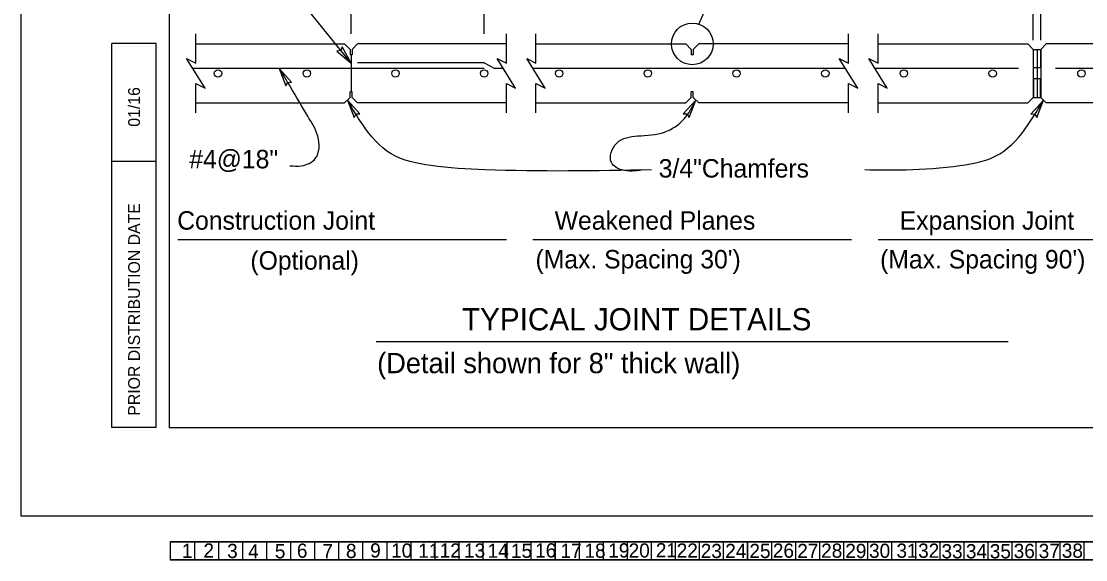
# Model space of a CAD drawing. Extents: x 0 to 2.83, y -0.03 to 1.83.
# Drawn here: x 0 to 0.75, y -0.031 to 0.349 of the extents above; entities that cross this region are included whole.
import ezdxf

# ---------------------------------------------------------------- set-up
doc = ezdxf.new("R2010")
doc.units = 0
for name, color, linetype in [('1', 7, 'Continuous'), ('10', 7, 'Continuous'), ('11', 7, 'Continuous'), ('12', 7, 'Continuous'), ('13', 7, 'Continuous'), ('14', 7, 'Continuous'), ('15', 7, 'Continuous'), ('16', 7, 'Continuous'), ('17', 7, 'Continuous'), ('18', 7, 'Continuous'), ('19', 7, 'Continuous'), ('2', 7, 'Continuous'), ('20', 7, 'Continuous'), ('21', 7, 'Continuous'), ('22', 7, 'Continuous'), ('23', 7, 'Continuous'), ('24', 7, 'Continuous'), ('25', 7, 'Continuous'), ('26', 7, 'Continuous'), ('27', 7, 'Continuous'), ('28', 7, 'Continuous'), ('29', 7, 'Continuous'), ('3', 7, 'Continuous'), ('30', 7, 'Continuous'), ('31', 7, 'Continuous'), ('32', 7, 'Continuous'), ('33', 7, 'Continuous'), ('34', 7, 'Continuous'), ('35', 7, 'Continuous'), ('36', 7, 'Continuous'), ('37', 7, 'Continuous'), ('38', 7, 'Continuous'), ('4', 7, 'Continuous'), ('5', 7, 'Continuous'), ('50', 7, 'Continuous'), ('51', 7, 'Continuous'), ('54', 7, 'Continuous'), ('55', 7, 'Continuous'), ('57', 7, 'Continuous'), ('6', 7, 'Continuous'), ('62', 7, 'Continuous'), ('63', 7, 'Continuous'), ('7', 7, 'Continuous'), ('8', 7, 'Continuous'), ('9', 7, 'Continuous')]:
    doc.layers.add(name, color=color, linetype=linetype)

msp = doc.modelspace()

# ---------------------------------------------------------------- linework, layer by layer
at = {"layer": '50'}
for p, q in [((0.47716, 0.34686), (0.50685, 0.41239)), ((0.12292, 0.33297), (0.22773, 0.33297)), ((0.22773, 0.33297), (0.23164, 0.32906)), ((0.23686, 0.33297), (0.23294, 0.32906)), ((0.34167, 0.33297), (0.23686, 0.33297)), ((0.3625, 0.33297), (0.46796, 0.33297)), ((0.46796, 0.33297), (0.47187, 0.32906)), ((0.46796, 0.33297), (0.47187, 0.32906)), ((0.4771, 0.33297), (0.47318, 0.32906)), ((0.4771, 0.33297), (0.47318, 0.32906)), ((0.58255, 0.33297), (0.4771, 0.33297)), ((0.60339, 0.33297), (0.70886, 0.33297)), ((0.70886, 0.33297), (0.71276, 0.32906)), ((0.72188, 0.33297), (0.71797, 0.32906)), ((0.82735, 0.33297), (0.72188, 0.33297)), ((0.23164, 0.32906), (0.23164, 0.32514)), ((0.23294, 0.32514), (0.23164, 0.32514)), ((0.23229, 0.32514), (0.23229, 0.29913)), ((0.23294, 0.32906), (0.23294, 0.32514)), ((0.47187, 0.32906), (0.47187, 0.32514)), ((0.47187, 0.32906), (0.47187, 0.32514)), ((0.47318, 0.32514), (0.47187, 0.32514)), ((0.47318, 0.32514), (0.47187, 0.32514)), ((0.47318, 0.32906), (0.47318, 0.32514)), ((0.47318, 0.32906), (0.47318, 0.32514)), ((0.71276, 0.32906), (0.71276, 0.29521)), ((0.71537, 0.32906), (0.71537, 0.29521)), ((0.71797, 0.32906), (0.71797, 0.29521)), ((0.22773, 0.2913), (0.23164, 0.29521)), ((0.23164, 0.29521), (0.23164, 0.29913)), ((0.23294, 0.29913), (0.23164, 0.29913)), ((0.23294, 0.29521), (0.23294, 0.29913)), ((0.23686, 0.2913), (0.23294, 0.29521)), ((0.46796, 0.2913), (0.47187, 0.29521)), ((0.46796, 0.2913), (0.47187, 0.29521)), ((0.47187, 0.29521), (0.47187, 0.29913)), ((0.47318, 0.29913), (0.47187, 0.29913)), ((0.47187, 0.29521), (0.47187, 0.29913)), ((0.47318, 0.29913), (0.47187, 0.29913)), ((0.47318, 0.29521), (0.47318, 0.29913)), ((0.47318, 0.29521), (0.47318, 0.29913)), ((0.4771, 0.2913), (0.47318, 0.29521)), ((0.4771, 0.2913), (0.47318, 0.29521)), ((0.70886, 0.2913), (0.71276, 0.29521)), ((0.72188, 0.2913), (0.71797, 0.29521)), ((0.12292, 0.2913), (0.22773, 0.2913)), ((0.34167, 0.2913), (0.23686, 0.2913)), ((0.3625, 0.2913), (0.46796, 0.2913)), ((0.58255, 0.2913), (0.4771, 0.2913)), ((0.60339, 0.2913), (0.70886, 0.2913)), ((0.82735, 0.2913), (0.72188, 0.2913))]:
    msp.add_line(p, q, dxfattribs=at)
for points in [[(0.71791, 0.32906), (0.71791, 0.31604), (0.71282, 0.31604), (0.71282, 0.32906)], [(0.71791, 0.29521), (0.71791, 0.30823), (0.71282, 0.30823), (0.71282, 0.29521)]]:
    msp.add_lwpolyline(points, close=True, dxfattribs=at)
msp.add_circle((0.47257, 0.33293), 0.01467, dxfattribs=at)
at = {"layer": '51'}
for p, q in [((0.32604, 0.31561), (0.12077, 0.31561)), ((0.32604, 0.31951), (0.23686, 0.31951)), ((0.32604, 0.31951), (0.33341, 0.31561)), ((0.33952, 0.31561), (0.33341, 0.31561)), ((0.5804, 0.31561), (0.36035, 0.31561)), ((0.70235, 0.31561), (0.60123, 0.31561)), ((0.82519, 0.31561), (0.72839, 0.31561))]:
    msp.add_line(p, q, dxfattribs=at)
for centre in [(0.13854, 0.31213), (0.20104, 0.31213), (0.26354, 0.31213), (0.32604, 0.31213), (0.37878, 0.31213), (0.44128, 0.31213), (0.50378, 0.31213), (0.56628, 0.31213), (0.62162, 0.31213), (0.68412, 0.31213), (0.74662, 0.31213)]:
    msp.add_circle(centre, 0.0026, dxfattribs=at)
at = {"layer": '54'}
for points in [[(0.23229, 0.31939), (0.22594, 0.33097), (0.22505, 0.3283), (0.22233, 0.32784)], [(0.18161, 0.31561), (0.1864, 0.3033), (0.18763, 0.30583), (0.19039, 0.30593)], [(0.22968, 0.29326), (0.23454, 0.28097), (0.23575, 0.28351), (0.23851, 0.28363)], [(0.47514, 0.29326), (0.46617, 0.28356), (0.46899, 0.28356), (0.47029, 0.28113)], [(0.71992, 0.29325), (0.71104, 0.28348), (0.71385, 0.28351), (0.71517, 0.28109)]]:
    msp.add_lwpolyline(points, close=True, dxfattribs=at)
at = {"layer": '55'}
for p, q in [((0.23229, 0.3401), (0.23229, 0.37681)), ((0.32604, 0.3401), (0.32604, 0.37681)), ((0.71276, 0.33555), (0.71276, 0.37681)), ((0.71797, 0.33555), (0.71797, 0.37681)), ((0.23229, 0.31939), (0.19647, 0.36376)), ((0.12292, 0.31937), (0.12292, 0.3401)), ((0.34167, 0.31937), (0.34167, 0.3401)), ((0.3625, 0.31937), (0.3625, 0.3401)), ((0.58255, 0.31937), (0.58255, 0.3401)), ((0.60339, 0.31937), (0.60339, 0.3401)), ((0.12943, 0.30164), (0.11641, 0.32263)), ((0.11641, 0.32263), (0.12292, 0.31937)), ((0.34818, 0.30164), (0.33516, 0.32263)), ((0.33516, 0.32263), (0.34167, 0.31937)), ((0.36901, 0.30164), (0.35599, 0.32263)), ((0.35599, 0.32263), (0.3625, 0.31937)), ((0.58906, 0.30164), (0.57604, 0.32263)), ((0.57604, 0.32263), (0.58255, 0.31937)), ((0.6099, 0.30164), (0.59688, 0.32263)), ((0.59688, 0.32263), (0.60339, 0.31937)), ((0.12292, 0.28426), (0.12292, 0.3049)), ((0.12292, 0.3049), (0.12943, 0.30164)), ((0.34167, 0.28426), (0.34167, 0.3049)), ((0.34167, 0.3049), (0.34818, 0.30164)), ((0.3625, 0.28426), (0.3625, 0.3049)), ((0.3625, 0.3049), (0.36901, 0.30164)), ((0.58255, 0.28426), (0.58255, 0.3049)), ((0.58255, 0.3049), (0.58906, 0.30164)), ((0.60339, 0.28426), (0.60339, 0.3049)), ((0.60339, 0.3049), (0.6099, 0.30164))]:
    msp.add_line(p, q, dxfattribs=at)
for points in [[(0.18912, 0.24701), (0.19726, 0.24701), (0.20707, 0.25202), (0.20874, 0.26788), (0.20185, 0.28186), (0.18954, 0.30272), (0.18161, 0.31561)], [(0.44389, 0.24405), (0.32652, 0.24419), (0.28855, 0.24713), (0.26048, 0.25542), (0.24043, 0.27601), (0.22968, 0.29326)], [(0.43739, 0.24404), (0.42298, 0.24403), (0.41561, 0.24934), (0.41937, 0.26293), (0.43411, 0.26801), (0.45311, 0.2708), (0.46671, 0.27997), (0.47514, 0.29326)], [(0.59404, 0.24426), (0.62309, 0.24419), (0.66105, 0.24713), (0.68912, 0.25542), (0.70918, 0.27601), (0.71992, 0.29325)]]:
    msp.add_spline(points, degree=3, dxfattribs=at)
at = {"layer": '57'}
for p, q in [((0.1102, 0.19492), (0.34167, 0.19492)), ((0.36023, 0.19492), (0.58482, 0.19492)), ((0.60339, 0.19492), (0.82746, 0.19492)), ((0.24991, 0.12316), (0.69514, 0.12316))]:
    msp.add_line(p, q, dxfattribs=at)
at = {"layer": '62'}
for p, q in [((0.10494, -0.01804), (1.17174, -0.01804)), ((0.10494, -0.01804), (0.10494, -0.03074)), ((0.10496, -0.0181), (1.17175, -0.0181)), ((0.10496, -0.0181), (0.10496, -0.0308)), ((0.12188, -0.01804), (0.12188, -0.03074)), ((0.12189, -0.0181), (0.12189, -0.0308)), ((0.13881, -0.01804), (0.13881, -0.03074)), ((0.13882, -0.0181), (0.13882, -0.0308)), ((0.15574, -0.01804), (0.15574, -0.03074)), ((0.15576, -0.0181), (0.15576, -0.0308)), ((0.17267, -0.01804), (0.17267, -0.03074)), ((0.17269, -0.0181), (0.17269, -0.0308)), ((0.18961, -0.01804), (0.18961, -0.03074)), ((0.18962, -0.0181), (0.18962, -0.0308)), ((0.20654, -0.01804), (0.20654, -0.03074)), ((0.20656, -0.0181), (0.20656, -0.0308)), ((0.22348, -0.01804), (0.22348, -0.03074)), ((0.22349, -0.0181), (0.22349, -0.0308)), ((0.24041, -0.01804), (0.24041, -0.03074)), ((0.24042, -0.0181), (0.24042, -0.0308)), ((0.25734, -0.01804), (0.25734, -0.03074)), ((0.25736, -0.0181), (0.25736, -0.0308)), ((0.27427, -0.01804), (0.27427, -0.03074)), ((0.27429, -0.0181), (0.27429, -0.0308)), ((0.29121, -0.01804), (0.29121, -0.03074)), ((0.29122, -0.0181), (0.29122, -0.0308)), ((0.30814, -0.01804), (0.30814, -0.03074)), ((0.30816, -0.0181), (0.30816, -0.0308)), ((0.32508, -0.01804), (0.32508, -0.03074)), ((0.32509, -0.0181), (0.32509, -0.0308)), ((0.34201, -0.01804), (0.34201, -0.03074)), ((0.34202, -0.0181), (0.34202, -0.0308)), ((0.35894, -0.01804), (0.35894, -0.03074)), ((0.35896, -0.0181), (0.35896, -0.0308)), ((0.37588, -0.01804), (0.37588, -0.03074)), ((0.37589, -0.0181), (0.37589, -0.0308)), ((0.39281, -0.01804), (0.39281, -0.03074)), ((0.39282, -0.0181), (0.39282, -0.0308)), ((0.40974, -0.01804), (0.40974, -0.03074)), ((0.40976, -0.0181), (0.40976, -0.0308)), ((0.42668, -0.01804), (0.42668, -0.03074)), ((0.42669, -0.0181), (0.42669, -0.0308)), ((0.44361, -0.01804), (0.44361, -0.03074)), ((0.44362, -0.0181), (0.44362, -0.0308)), ((0.46054, -0.01804), (0.46054, -0.03074)), ((0.46056, -0.0181), (0.46056, -0.0308)), ((0.47748, -0.01804), (0.47748, -0.03074)), ((0.47749, -0.0181), (0.47749, -0.0308)), ((0.49441, -0.01804), (0.49441, -0.03074)), ((0.49442, -0.0181), (0.49442, -0.0308)), ((0.51134, -0.01804), (0.51134, -0.03074)), ((0.51136, -0.0181), (0.51136, -0.0308)), ((0.52828, -0.01804), (0.52828, -0.03074)), ((0.52829, -0.0181), (0.52829, -0.0308)), ((0.54521, -0.01804), (0.54521, -0.03074)), ((0.54522, -0.0181), (0.54522, -0.0308)), ((0.56214, -0.01804), (0.56214, -0.03074)), ((0.56216, -0.0181), (0.56216, -0.0308)), ((0.57908, -0.01804), (0.57908, -0.03074)), ((0.57909, -0.0181), (0.57909, -0.0308)), ((0.59601, -0.01804), (0.59601, -0.03074)), ((0.59602, -0.0181), (0.59602, -0.0308)), ((0.61294, -0.01804), (0.61294, -0.03074)), ((0.61296, -0.0181), (0.61296, -0.0308)), ((0.62988, -0.01804), (0.62988, -0.03074)), ((0.62989, -0.0181), (0.62989, -0.0308)), ((0.64681, -0.01804), (0.64681, -0.03074)), ((0.64682, -0.0181), (0.64682, -0.0308)), ((0.66374, -0.01804), (0.66374, -0.03074)), ((0.66376, -0.0181), (0.66376, -0.0308)), ((0.68068, -0.01804), (0.68068, -0.03074)), ((0.68069, -0.0181), (0.68069, -0.0308)), ((0.69761, -0.01804), (0.69761, -0.03074)), ((0.69762, -0.0181), (0.69762, -0.0308)), ((0.71454, -0.01804), (0.71454, -0.03074)), ((0.71456, -0.0181), (0.71456, -0.0308)), ((0.73147, -0.01804), (0.73147, -0.03074)), ((0.73149, -0.0181), (0.73149, -0.0308)), ((0.74841, -0.01804), (0.74841, -0.03074)), ((0.74842, -0.0181), (0.74842, -0.0308)), ((0.10494, -0.03074), (1.17174, -0.03074)), ((0.10496, -0.0308), (1.17175, -0.0308))]:
    msp.add_line(p, q, dxfattribs=at)
at = {"layer": '63'}
for p, q in [((0, 0), (0, 1.83333)), ((0.06381, 0.06244), (0.06381, 0.33328)), ((0.09506, 0.33328), (0.06381, 0.33328)), ((0.09506, 0.06244), (0.09506, 0.33328)), ((0.09506, 0.24994), (0.06381, 0.24994)), ((0.09506, 0.06244), (0.06381, 0.06244)), ((2.83333, 0), (0, 0))]:
    msp.add_line(p, q, dxfattribs=at)
msp.add_lwpolyline([(2.72918, 1.77077), (0.10418, 1.77077), (0.10418, 0.06244), (2.72918, 0.06244)], close=True, dxfattribs=at)

# ---------------------------------------------------------------- texts
at = {"layer": '1'}
for p in [(0.11316, -0.02944), (0.11317, -0.02949)]:
    msp.add_text('1', height=0.01, dxfattribs=at).set_placement(p)
at = {"layer": '10'}
for p in [(0.26046, -0.02928), (0.26047, -0.02934)]:
    msp.add_text('10', height=0.01, dxfattribs=at).set_placement(p)
at = {"layer": '11'}
for p in [(0.2796, -0.02937), (0.27961, -0.02942)]:
    msp.add_text('11', height=0.01, dxfattribs=at).set_placement(p)
at = {"layer": '12'}
for p in [(0.29469, -0.02925), (0.29471, -0.0293)]:
    msp.add_text('12', height=0.01, dxfattribs=at).set_placement(p)
at = {"layer": '13'}
for p in [(0.31181, -0.02928), (0.31182, -0.02933)]:
    msp.add_text('13', height=0.01, dxfattribs=at).set_placement(p)
at = {"layer": '14'}
for p in [(0.32844, -0.02939), (0.32846, -0.02944)]:
    msp.add_text('14', height=0.01, dxfattribs=at).set_placement(p)
at = {"layer": '15'}
for p in [(0.34488, -0.02946), (0.34489, -0.02951)]:
    msp.add_text('15', height=0.01, dxfattribs=at).set_placement(p)
at = {"layer": '16'}
for p in [(0.3619, -0.02918), (0.36191, -0.02923)]:
    msp.add_text('16', height=0.01, dxfattribs=at).set_placement(p)
at = {"layer": '17'}
for p in [(0.3797, -0.02946), (0.37971, -0.02951)]:
    msp.add_text('17', height=0.01, dxfattribs=at).set_placement(p)
at = {"layer": '18'}
for p in [(0.39663, -0.02938), (0.39664, -0.02943)]:
    msp.add_text('18', height=0.01, dxfattribs=at).set_placement(p)
at = {"layer": '19'}
for p in [(0.4134, -0.02918), (0.41342, -0.02923)]:
    msp.add_text('19', height=0.01, dxfattribs=at).set_placement(p)
at = {"layer": '2'}
for p in [(0.12828, -0.02928), (0.12829, -0.02934)]:
    msp.add_text('2', height=0.01, dxfattribs=at).set_placement(p)
at = {"layer": '20'}
for p in [(0.42774, -0.02926), (0.42776, -0.02931)]:
    msp.add_text('20', height=0.01, dxfattribs=at).set_placement(p)
at = {"layer": '21'}
for p in [(0.44688, -0.02909), (0.44689, -0.02914)]:
    msp.add_text('21', height=0.01, dxfattribs=at).set_placement(p)
at = {"layer": '22'}
for p in [(0.46158, -0.02929), (0.46159, -0.02934)]:
    msp.add_text('22', height=0.01, dxfattribs=at).set_placement(p)
at = {"layer": '23'}
for p in [(0.47852, -0.02958), (0.47853, -0.02963)]:
    msp.add_text('23', height=0.01, dxfattribs=at).set_placement(p)
at = {"layer": '24'}
for p in [(0.49576, -0.02958), (0.49577, -0.02963)]:
    msp.add_text('24', height=0.01, dxfattribs=at).set_placement(p)
at = {"layer": '25'}
for p in [(0.51281, -0.02958), (0.51282, -0.02963)]:
    msp.add_text('25', height=0.01, dxfattribs=at).set_placement(p)
at = {"layer": '26'}
for p in [(0.52931, -0.02936), (0.52932, -0.02941)]:
    msp.add_text('26', height=0.01, dxfattribs=at).set_placement(p)
at = {"layer": '27'}
for p in [(0.54648, -0.02958), (0.54649, -0.02963)]:
    msp.add_text('27', height=0.01, dxfattribs=at).set_placement(p)
at = {"layer": '28'}
for p in [(0.56333, -0.02938), (0.56334, -0.02943)]:
    msp.add_text('28', height=0.01, dxfattribs=at).set_placement(p)
at = {"layer": '29'}
for p in [(0.58032, -0.02956), (0.58034, -0.02961)]:
    msp.add_text('29', height=0.01, dxfattribs=at).set_placement(p)
at = {"layer": '3'}
for p in [(0.145, -0.02955), (0.14501, -0.02961)]:
    msp.add_text('3', height=0.01, dxfattribs=at).set_placement(p)
at = {"layer": '30'}
for p in [(0.59706, -0.02946), (0.59707, -0.02951)]:
    msp.add_text('30', height=0.01, dxfattribs=at).set_placement(p)
at = {"layer": '31'}
for p in [(0.61636, -0.02938), (0.61637, -0.02943)]:
    msp.add_text('31', height=0.01, dxfattribs=at).set_placement(p)
at = {"layer": '32'}
for p in [(0.63163, -0.02938), (0.63165, -0.02943)]:
    msp.add_text('32', height=0.01, dxfattribs=at).set_placement(p)
at = {"layer": '33'}
for p in [(0.64808, -0.02978), (0.64809, -0.02983)]:
    msp.add_text('33', height=0.01, dxfattribs=at).set_placement(p)
at = {"layer": '34'}
for p in [(0.66527, -0.02978), (0.66528, -0.02984)]:
    msp.add_text('34', height=0.01, dxfattribs=at).set_placement(p)
at = {"layer": '35'}
for p in [(0.68209, -0.02978), (0.68211, -0.02984)]:
    msp.add_text('35', height=0.01, dxfattribs=at).set_placement(p)
at = {"layer": '36'}
for p in [(0.69895, -0.02958), (0.69896, -0.02964)]:
    msp.add_text('36', height=0.01, dxfattribs=at).set_placement(p)
at = {"layer": '37'}
for p in [(0.71654, -0.02958), (0.71655, -0.02964)]:
    msp.add_text('37', height=0.01, dxfattribs=at).set_placement(p)
at = {"layer": '38'}
for p in [(0.73281, -0.02938), (0.73282, -0.02943)]:
    msp.add_text('38', height=0.01, dxfattribs=at).set_placement(p)
at = {"layer": '4'}
for p in [(0.15973, -0.02984), (0.15975, -0.0299)]:
    msp.add_text('4', height=0.01, dxfattribs=at).set_placement(p)
at = {"layer": '5'}
for p in [(0.17858, -0.02977), (0.17859, -0.02982)]:
    msp.add_text('5', height=0.01, dxfattribs=at).set_placement(p)
at = {"layer": '57'}
for s, height, p in [('#4@18"', 0.013017, (0.11833, 0.24518)), ('3/4"Chamfers', 0.0130167, (0.44894, 0.23867)), ('Construction Joint', 0.0130167, (0.10981, 0.20194)), ('Weakened Planes', 0.0130167, (0.37567, 0.20194)), ('Expansion Joint', 0.0130167, (0.61867, 0.20194)), ('(Optional)', 0.013017, (0.16136, 0.17376)), ("(Max. Spacing 30')", 0.0130167, (0.36214, 0.1746)), ("(Max. Spacing 90')", 0.0130167, (0.60486, 0.1746)), ('TYPICAL JOINT DETAILS', 0.015625, (0.31037, 0.13098)), ('(Detail shown for 8" thick wall)', 0.0143167, (0.25065, 0.10073))]:
    msp.add_text(s, height=height, dxfattribs=at).set_placement(p)
at = {"layer": '6'}
for p in [(0.19409, -0.02938), (0.19411, -0.02943)]:
    msp.add_text('6', height=0.01, dxfattribs=at).set_placement(p)
at = {"layer": '63'}
for s, height, p in [('01/16', 0.008333, (0.0836, 0.27453)), ('PRIOR DISTRIBUTION DATE', 0.0083333, (0.0836, 0.07078))]:
    msp.add_text(s, height=height, rotation=90, dxfattribs=at).set_placement(p)
at = {"layer": '7'}
for p in [(0.21211, -0.02964), (0.21212, -0.02969)]:
    msp.add_text('7', height=0.01, dxfattribs=at).set_placement(p)
at = {"layer": '8'}
for p in [(0.22865, -0.02958), (0.22866, -0.02963)]:
    msp.add_text('8', height=0.01, dxfattribs=at).set_placement(p)
at = {"layer": '9'}
for p in [(0.24573, -0.02921), (0.24574, -0.02926)]:
    msp.add_text('9', height=0.01, dxfattribs=at).set_placement(p)

doc.saveas('drawing.dxf')
